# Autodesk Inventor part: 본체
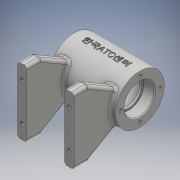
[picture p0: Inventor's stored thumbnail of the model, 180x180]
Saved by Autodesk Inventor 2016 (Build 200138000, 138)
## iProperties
Created: 2018-05
Part Number: 본체
Material: 일반
Document SubType Name: Modeling
Designer: 201-08
Density: 1 g/cm^3
Appearance: 기본값
Author: 201-08
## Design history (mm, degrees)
sketch "스케치1"
  geometry: C1 r 26 at (0, 0); 1 further point
  constraints: 1 centre point, 1 coincident
  dimensions: "d0" = 52 diameter of C1
extrude "돌출1" new body sketch "스케치1" stored distance "d2" = 70; taper "d3" = 0 deg
node "작업 평면2"
  node "작업 평면1"
sketch "스케치2"
  geometry: L1 (0, 0)-(-65, 0); L2 (-65, 0)-(-65, -35); L3 (-65, -35)-(-50, -35); L4 (-50, -35)-(10.622, 0); L5 (-65, 0)-(-65, 35); L6 (-65, 35)-(-50, 35); L7 (-50, 35)-(10.622, 0)
  constraints: 14 end point, 2 symmetric about line, 1 horizontal, 1 perpendicular, 1 point on line, 1 vertical
  dimensions: "d6" = 65 distance of L1.start L1.end; "d7" = 35 distance of L1.end L2.end; "d8" = 15 distance of L2.end L3.end; "d9" = 150 deg angle of L4 L3; "d10" = 30 deg angle of L6 L7 (derived)
extrude "돌출2" join sketch "스케치2" distance "d11" = 10; taper "d12" = 0 deg
sketch "스케치3"
  geometry: L1 (0, 70)-(0, 0) reference; L2 (0, 70)-(-10, 70) reference; L3 (-10, 0)-(-10, 70) reference; L4 (0, 0)-(-10, 0) reference; L5 (40, 70)-(40, 0) reference; L6 (40, 0)-(50, 0) reference; L7 (50, 0)-(50, 70) reference; L8 (40, 70)-(50, 70) reference; 5 further points
  constraints: 2 horizontal alignment, 2 vertical alignment
  dimensions: "d13" = 60 distance between parallel lines of L7 L3 (derived); "d14" = 40 distance of point (-5, 55) point (-5, 15); "d15" = 5 horizontal distance of L3.start point (-5, 15); "d16" = 20 vertical distance of point (20, 35) point (45, 55)
hole "구멍1" sketch "스케치3" at (-5, 55), (-5, 15), (45, 55), (45, 15) diameter "d17" = 4.134; stored, may be unused: countersink angle "d21" = 90 deg, drill point angle "d23" = 118 deg; dims "d18" = 8, "d19" = 4, "d20" = 2, "d22" = 10
fillet "모깎기1" dims "d24" = 3
sketch "스케치4"
  geometry: C1 r 14 at (0, 0); 1 further point
  constraints: 1 centre point, 1 coincident
  dimensions: "d25" = 28 diameter of C1
extrude "돌출3" cut sketch "스케치4" stored distance "d26" = 10; taper "d27" = 0 deg
sketch "스케치5"
  geometry: C1 r 16 at (0, 0); 1 further point
  constraints: 1 centre point, 1 coincident
  dimensions: "d28" = 32 diameter of C1
extrude "돌출4" cut sketch "스케치5" distance "d29" = 12; taper "d30" = 0 deg
sketch "스케치6"
  geometry: C1 r 21 at (0, 0); 1 further point
  constraints: 1 centre point, 1 coincident
  dimensions: "d31" = 42 diameter of C1
extrude "돌출5" cut sketch "스케치6" stored distance "d32" = 42; taper "d33" = 0 deg
fillet "모깎기2" dims "d34" = 0.3
fillet "모깎기3" dims "d35" = 3
node "작업 평면3"
sketch "스케치7"
  geometry: C1 r 5 at (0, 0); 1 further point
  constraints: 1 centre point, 1 coincident
  dimensions: "d36" = 10 diameter of C1
extrude "돌출6" join sketch "스케치7" stored distance "d37" = 6; taper "d38" = 0 deg
fillet "모깎기4" dims "d39" = 2
sketch "스케치8"
  geometry: 2 further points
  constraints: 1 coincident
hole "구멍2" sketch "스케치8" at (0, 0) diameter "d40" = 5.188; stored, may be unused: countersink angle "d44" = 90 deg, drill point angle "d46" = 118 deg; dims "d41" = 10, "d42" = 4, "d43" = 2, "d45" = 10
chamfer "모따기1" distance "d47" = 1; stored, may be unused: second distance "d48" = 2, angle "d49" = 45 deg
sketch "스케치9"
  geometry: L1 (0, 0)-(-21, 0); L2 (0, 0)-(-27.251, -9.919); L3 (0, 0)-(29, 0); 2 further points
  constraints: 6 end point, 2 horizontal, 1 coincident, 1 equal length, 1 point on line
  dimensions: "d78" = 29 distance of L2.start L2.end; "d80" = 20 deg angle of L1 L2
sketch "스케치12" dims "d66" = 42
  geometry: 6 further points
  constraints: 1 coincident, 1 vertical alignment, 7 other
  dimensions: "d69" = 360 deg dimension on point (0, 0) point (0, 21) (derived)
hole "구멍4" sketch "스케치12" at (0, 21), (-21, 0), (0, -21), (21, 0) diameter "d71" = 3.242; stored, may be unused: countersink angle "d75" = 90 deg, drill point angle "d77" = 118 deg; dims "d72" = 8, "d73" = 4, "d74" = 2, "d76" = 10
node "작업 평면5"
sketch "스케치13"
  geometry: C1 r 6 at (0, 0); 1 further point
  constraints: 1 centre point, 1 coincident
  dimensions: "d81" = 12 diameter of C1
extrude "돌출8" join sketch "스케치13" distance "d82" = 6; taper "d83" = 0 deg
fillet "모깎기6" dims "d84" = 2
sketch "스케치14"
  geometry: 2 further points
  constraints: 1 coincident
hole "구멍5" sketch "스케치14" at (0, 0) diameter "d85" = 5.188; stored, may be unused: countersink angle "d89" = 90 deg, drill point angle "d91" = 118 deg; dims "d86" = 10, "d87" = 4, "d88" = 2, "d90" = 10
node "작업 평면6"
sketch "스케치15"
  geometry: L1 (-35, 26)-(-35, -26) reference; 2 further points
  constraints: 1 other
  dimensions: "d92" = 35 distance from line of L1 point (0, 0); "d93" = 26 vertical distance of L1.start point (0, 0)
feature "엠보싱1" sketch "스케치15" dims "d10" = 30 deg (derived), "d94" = 0.5, "d95" = 0
node "솔리드1"
mirror "대칭1"
mirror "대칭2"
mirror "대칭3"
node "투영된 루프1"
node "투영된 루프2"
other parameters: "d4" = 0
